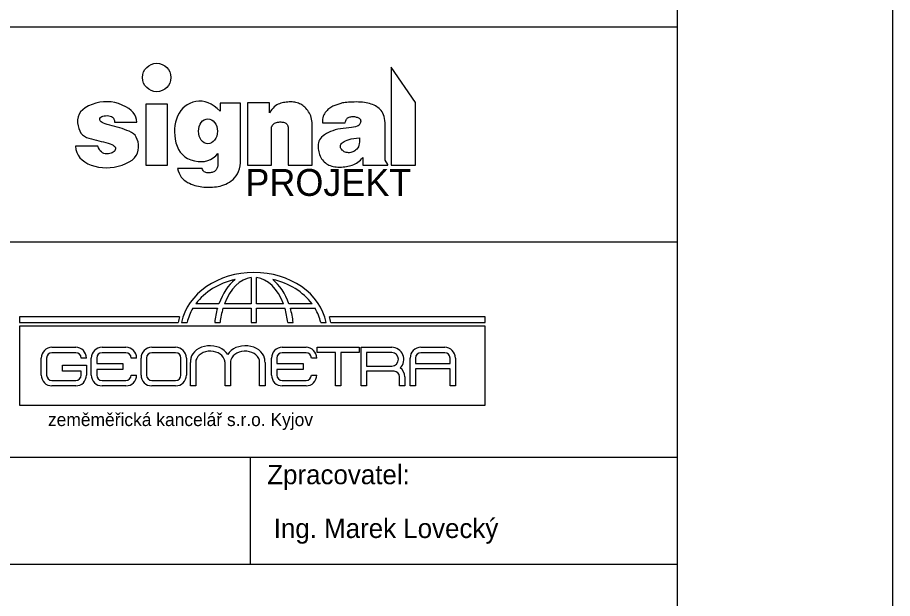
# Model space of a CAD drawing. Extents: x -553916 to -552953, y -1067470 to -1066637.
# Drawn here: x -553034.4 to -552953.1, y -1067311.4 to -1067257.4 of the extents above; entities that cross this region are included whole.
import ezdxf

# ---------------------------------------------------------------- set-up
doc = ezdxf.new("R2010")
doc.units = 0
for name, color, linetype in [('ROZPISKA', 7, 'Continuous'), ('Rozpiska_pole_1', 7, 'Continuous'), ('Rozpiska_pole_6', 7, 'Continuous'), ('Vrstva 1', 7, 'Continuous'), ('ZZZ - Razítko', 7, 'Continuous')]:
    doc.layers.add(name, color=color, linetype=linetype)

msp = doc.modelspace()

# ---------------------------------------------------------------- linework, layer by layer
at = {"layer": 'ROZPISKA'}
for points in [[(-552997.445, -1067271.147), (-552997.445, -1067265.307), (-552999.685, -1067262.027), (-552999.685, -1067271.147), (-552997.445, -1067271.147)], [(-553026.174, -1067271.382), (-553025.812, -1067271.366), (-553025.445, -1067271.318), (-553025.074, -1067271.239), (-553024.698, -1067271.128), (-553024.344, -1067270.992), (-553024.036, -1067270.836), (-553023.775, -1067270.66), (-553023.561, -1067270.464), (-553023.393, -1067270.248), (-553023.273, -1067270.012), (-553023.199, -1067269.756), (-553023.173, -1067269.481), (-553023.183, -1067269.207), (-553023.222, -1067268.958), (-553023.288, -1067268.734), (-553023.382, -1067268.535), (-553023.503, -1067268.36), (-553023.652, -1067268.21), (-553023.829, -1067268.084), (-553024.034, -1067267.984), (-553024.253, -1067267.898), (-553024.475, -1067267.816), (-553024.699, -1067267.738), (-553024.926, -1067267.666), (-553025.155, -1067267.597), (-553025.386, -1067267.533), (-553025.619, -1067267.473), (-553025.855, -1067267.418), (-553026.077, -1067267.363), (-553026.268, -1067267.304), (-553026.428, -1067267.241), (-553026.559, -1067267.174), (-553026.659, -1067267.102), (-553026.728, -1067267.027), (-553026.767, -1067266.948), (-553026.776, -1067266.865), (-553026.759, -1067266.785), (-553026.723, -1067266.717), (-553026.667, -1067266.659), (-553026.591, -1067266.611), (-553026.495, -1067266.575), (-553026.379, -1067266.55), (-553026.244, -1067266.535), (-553026.088, -1067266.531), (-553025.933, -1067266.542), (-553025.798, -1067266.571), (-553025.683, -1067266.619), (-553025.588, -1067266.684), (-553025.513, -1067266.768), (-553025.459, -1067266.87), (-553025.424, -1067266.991), (-553025.41, -1067267.129), (-553023.331, -1067267.129), (-553023.35, -1067266.888), (-553023.412, -1067266.658), (-553023.517, -1067266.441), (-553023.665, -1067266.237), (-553023.856, -1067266.045), (-553024.09, -1067265.866), (-553024.366, -1067265.7), (-553024.686, -1067265.547), (-553025.028, -1067265.417), (-553025.373, -1067265.323), (-553025.721, -1067265.263), (-553026.071, -1067265.238), (-553026.424, -1067265.248), (-553026.779, -1067265.293), (-553027.138, -1067265.373), (-553027.498, -1067265.487), (-553027.836, -1067265.63), (-553028.126, -1067265.792), (-553028.366, -1067265.976), (-553028.559, -1067266.18), (-553028.702, -1067266.404), (-553028.797, -1067266.649), (-553028.843, -1067266.914), (-553028.841, -1067267.2), (-553028.801, -1067267.482), (-553028.735, -1067267.734), (-553028.643, -1067267.956), (-553028.524, -1067268.149), (-553028.38, -1067268.312), (-553028.209, -1067268.446), (-553028.012, -1067268.55), (-553027.788, -1067268.625), (-553027.553, -1067268.685), (-553027.322, -1067268.745), (-553027.095, -1067268.804), (-553026.871, -1067268.863), (-553026.65, -1067268.921), (-553026.434, -1067268.98), (-553026.221, -1067269.038), (-553026.011, -1067269.096), (-553025.819, -1067269.156), (-553025.657, -1067269.22), (-553025.527, -1067269.289), (-553025.427, -1067269.362), (-553025.359, -1067269.44), (-553025.321, -1067269.523), (-553025.314, -1067269.609), (-553025.338, -1067269.701), (-553025.384, -1067269.789), (-553025.445, -1067269.865), (-553025.521, -1067269.93), (-553025.611, -1067269.983), (-553025.715, -1067270.024), (-553025.833, -1067270.054), (-553025.966, -1067270.073), (-553026.113, -1067270.079), (-553026.262, -1067270.069), (-553026.398, -1067270.036), (-553026.521, -1067269.98), (-553026.632, -1067269.902), (-553026.731, -1067269.8), (-553026.818, -1067269.677), (-553026.892, -1067269.53), (-553026.953, -1067269.362), (-553029.034, -1067269.362), (-553028.99, -1067269.668), (-553028.906, -1067269.951), (-553028.783, -1067270.208), (-553028.621, -1067270.442), (-553028.418, -1067270.652), (-553028.177, -1067270.837), (-553027.895, -1067270.998), (-553027.574, -1067271.134), (-553027.231, -1067271.243), (-553026.883, -1067271.321), (-553026.531, -1067271.367), (-553026.174, -1067271.382)], [(-553016.626, -1067273.189), (-553016.457, -1067273.186), (-553016.287, -1067273.177), (-553016.115, -1067273.164), (-553015.942, -1067273.145), (-553015.768, -1067273.119), (-553015.594, -1067273.08), (-553015.42, -1067273.028), (-553015.246, -1067272.965), (-553015.073, -1067272.89), (-553014.9, -1067272.802), (-553014.728, -1067272.702), (-553014.556, -1067272.59), (-553014.391, -1067272.461), (-553014.243, -1067272.308), (-553014.11, -1067272.132), (-553013.994, -1067271.933), (-553013.893, -1067271.711), (-553013.808, -1067271.466), (-553013.739, -1067271.198), (-553013.685, -1067270.907), (-553013.685, -1067265.387), (-553015.605, -1067265.387), (-553015.605, -1067266.107), (-553015.871, -1067265.853), (-553016.142, -1067265.64), (-553016.416, -1067265.468), (-553016.695, -1067265.337), (-553016.978, -1067265.247), (-553017.266, -1067265.198), (-553017.557, -1067265.19), (-553017.853, -1067265.224), (-553018.14, -1067265.292), (-553018.406, -1067265.389), (-553018.649, -1067265.514), (-553018.871, -1067265.668), (-553019.071, -1067265.85), (-553019.249, -1067266.061), (-553019.406, -1067266.301), (-553019.541, -1067266.568), (-553019.651, -1067266.854), (-553019.736, -1067267.147), (-553019.795, -1067267.447), (-553019.828, -1067267.755), (-553019.835, -1067268.069), (-553019.816, -1067268.391), (-553019.772, -1067268.72), (-553019.701, -1067269.056), (-553019.601, -1067269.379), (-553019.468, -1067269.67), (-553019.303, -1067269.928), (-553019.105, -1067270.154), (-553018.874, -1067270.346), (-553018.611, -1067270.506), (-553018.314, -1067270.634), (-553017.986, -1067270.728), (-553017.649, -1067270.786), (-553017.331, -1067270.804), (-553017.03, -1067270.78), (-553016.747, -1067270.716), (-553016.482, -1067270.612), (-553016.235, -1067270.466), (-553016.005, -1067270.28), (-553015.793, -1067270.053), (-553015.793, -1067271.13), (-553015.812, -1067271.217), (-553015.835, -1067271.299), (-553015.862, -1067271.375), (-553015.895, -1067271.445), (-553015.931, -1067271.51), (-553015.972, -1067271.568), (-553016.018, -1067271.621), (-553016.067, -1067271.669), (-553016.123, -1067271.71), (-553016.186, -1067271.747), (-553016.256, -1067271.778), (-553016.333, -1067271.803), (-553016.417, -1067271.823), (-553016.508, -1067271.838), (-553016.606, -1067271.847), (-553016.711, -1067271.851), (-553016.815, -1067271.846), (-553016.908, -1067271.827), (-553016.991, -1067271.796), (-553017.064, -1067271.751), (-553017.127, -1067271.692), (-553017.18, -1067271.621), (-553017.222, -1067271.536), (-553017.254, -1067271.438), (-553019.562, -1067271.438), (-553019.492, -1067271.665), (-553019.409, -1067271.874), (-553019.312, -1067272.064), (-553019.201, -1067272.236), (-553019.077, -1067272.388), (-553018.938, -1067272.522), (-553018.786, -1067272.637), (-553018.62, -1067272.734), (-553018.448, -1067272.817), (-553018.277, -1067272.891), (-553018.108, -1067272.956), (-553017.94, -1067273.013), (-553017.774, -1067273.062), (-553017.609, -1067273.102), (-553017.446, -1067273.133), (-553017.284, -1067273.155), (-553017.122, -1067273.171), (-553016.958, -1067273.182), (-553016.793, -1067273.188), (-553016.626, -1067273.189)], [(-553007.045, -1067271.147), (-553007.045, -1067267.347), (-553007.048, -1067267.177), (-553007.062, -1067267.014), (-553007.087, -1067266.857), (-553007.123, -1067266.707), (-553007.169, -1067266.564), (-553007.226, -1067266.427), (-553007.294, -1067266.297), (-553007.372, -1067266.173), (-553007.457, -1067266.057), (-553007.544, -1067265.949), (-553007.633, -1067265.849), (-553007.724, -1067265.757), (-553007.817, -1067265.674), (-553007.912, -1067265.598), (-553008.009, -1067265.531), (-553008.108, -1067265.473), (-553008.211, -1067265.421), (-553008.317, -1067265.377), (-553008.428, -1067265.34), (-553008.543, -1067265.309), (-553008.662, -1067265.286), (-553008.786, -1067265.269), (-553008.914, -1067265.259), (-553009.046, -1067265.257), (-553009.18, -1067265.26), (-553009.312, -1067265.268), (-553009.444, -1067265.281), (-553009.574, -1067265.299), (-553009.703, -1067265.322), (-553009.831, -1067265.35), (-553009.957, -1067265.382), (-553010.083, -1067265.42), (-553010.206, -1067265.468), (-553010.328, -1067265.533), (-553010.447, -1067265.614), (-553010.563, -1067265.712), (-553010.677, -1067265.826), (-553010.789, -1067265.957), (-553010.898, -1067266.104), (-553011.005, -1067266.267), (-553011.005, -1067265.347), (-553013.045, -1067265.347), (-553013.045, -1067271.147), (-553010.805, -1067271.147), (-553010.805, -1067267.587), (-553010.771, -1067267.496), (-553010.726, -1067267.415), (-553010.672, -1067267.344), (-553010.608, -1067267.283), (-553010.534, -1067267.232), (-553010.45, -1067267.191), (-553010.356, -1067267.16), (-553010.252, -1067267.139), (-553010.146, -1067267.126), (-553010.045, -1067267.119), (-553009.95, -1067267.118), (-553009.859, -1067267.124), (-553009.774, -1067267.135), (-553009.695, -1067267.153), (-553009.62, -1067267.176), (-553009.551, -1067267.206), (-553009.489, -1067267.241), (-553009.435, -1067267.279), (-553009.389, -1067267.321), (-553009.352, -1067267.367), (-553009.323, -1067267.417), (-553009.302, -1067267.47), (-553009.289, -1067267.527), (-553009.285, -1067267.587), (-553009.285, -1067271.147), (-553007.045, -1067271.147)], [(-553004.482, -1067271.311), (-553004.321, -1067271.308), (-553004.163, -1067271.3), (-553004.01, -1067271.285), (-553003.861, -1067271.265), (-553003.716, -1067271.24), (-553003.576, -1067271.208), (-553003.44, -1067271.171), (-553003.308, -1067271.128), (-553003.18, -1067271.076), (-553003.053, -1067271.015), (-553002.927, -1067270.943), (-553002.804, -1067270.861), (-553002.682, -1067270.768), (-553002.561, -1067270.665), (-553002.442, -1067270.551), (-553002.325, -1067270.427), (-553002.325, -1067271.147), (-553000.005, -1067271.147), (-553000.005, -1067271.067), (-553000.245, -1067270.667), (-553000.245, -1067267.187), (-553000.272, -1067266.983), (-553000.307, -1067266.792), (-553000.353, -1067266.617), (-553000.408, -1067266.456), (-553000.472, -1067266.309), (-553000.546, -1067266.177), (-553000.63, -1067266.059), (-553000.723, -1067265.955), (-553000.824, -1067265.863), (-553000.931, -1067265.777), (-553001.045, -1067265.698), (-553001.165, -1067265.626), (-553001.291, -1067265.561), (-553001.423, -1067265.503), (-553001.562, -1067265.452), (-553001.707, -1067265.408), (-553001.859, -1067265.37), (-553002.018, -1067265.338), (-553002.184, -1067265.311), (-553002.358, -1067265.29), (-553002.538, -1067265.275), (-553002.726, -1067265.266), (-553002.922, -1067265.262), (-553003.124, -1067265.265), (-553003.323, -1067265.271), (-553003.507, -1067265.279), (-553003.676, -1067265.289), (-553003.83, -1067265.302), (-553003.97, -1067265.317), (-553004.095, -1067265.334), (-553004.206, -1067265.354), (-553004.301, -1067265.375), (-553004.39, -1067265.399), (-553004.479, -1067265.425), (-553004.569, -1067265.452), (-553004.66, -1067265.482), (-553004.751, -1067265.513), (-553004.844, -1067265.547), (-553004.936, -1067265.582), (-553005.03, -1067265.62), (-553005.123, -1067265.661), (-553005.215, -1067265.71), (-553005.306, -1067265.765), (-553005.397, -1067265.827), (-553005.486, -1067265.896), (-553005.574, -1067265.972), (-553005.661, -1067266.055), (-553005.747, -1067266.144), (-553005.827, -1067266.242), (-553005.897, -1067266.349), (-553005.955, -1067266.465), (-553006.003, -1067266.591), (-553006.04, -1067266.726), (-553006.066, -1067266.87), (-553006.081, -1067267.024), (-553006.085, -1067267.187), (-553003.965, -1067267.187), (-553003.95, -1067267.091), (-553003.926, -1067267.004), (-553003.893, -1067266.926), (-553003.851, -1067266.857), (-553003.801, -1067266.797), (-553003.743, -1067266.747), (-553003.675, -1067266.705), (-553003.599, -1067266.673), (-553003.519, -1067266.649), (-553003.438, -1067266.631), (-553003.356, -1067266.619), (-553003.274, -1067266.615), (-553003.192, -1067266.616), (-553003.108, -1067266.625), (-553003.025, -1067266.639), (-553002.94, -1067266.661), (-553002.86, -1067266.686), (-553002.789, -1067266.714), (-553002.726, -1067266.744), (-553002.673, -1067266.776), (-553002.627, -1067266.81), (-553002.591, -1067266.846), (-553002.563, -1067266.885), (-553002.545, -1067266.925), (-553002.533, -1067266.968), (-553002.528, -1067267.014), (-553002.529, -1067267.063), (-553002.537, -1067267.114), (-553002.55, -1067267.168), (-553002.57, -1067267.225), (-553002.597, -1067267.285), (-553002.629, -1067267.348), (-553002.68, -1067267.409), (-553002.761, -1067267.465), (-553002.872, -1067267.515), (-553003.014, -1067267.561), (-553003.186, -1067267.601), (-553003.388, -1067267.636), (-553003.621, -1067267.665), (-553003.884, -1067267.689), (-553004.156, -1067267.716), (-553004.415, -1067267.753), (-553004.662, -1067267.801), (-553004.897, -1067267.86), (-553005.12, -1067267.929), (-553005.331, -1067268.008), (-553005.529, -1067268.098), (-553005.715, -1067268.199), (-553005.884, -1067268.307), (-553006.032, -1067268.42), (-553006.16, -1067268.537), (-553006.266, -1067268.659), (-553006.352, -1067268.785), (-553006.417, -1067268.915), (-553006.461, -1067269.051), (-553006.484, -1067269.19), (-553006.492, -1067269.332), (-553006.491, -1067269.472), (-553006.481, -1067269.611), (-553006.462, -1067269.749), (-553006.434, -1067269.885), (-553006.397, -1067270.021), (-553006.351, -1067270.155), (-553006.296, -1067270.288), (-553006.233, -1067270.417), (-553006.163, -1067270.536), (-553006.086, -1067270.646), (-553006.002, -1067270.748), (-553005.911, -1067270.84), (-553005.814, -1067270.924), (-553005.709, -1067270.999), (-553005.598, -1067271.065), (-553005.48, -1067271.123), (-553005.356, -1067271.173), (-553005.226, -1067271.215), (-553005.089, -1067271.25), (-553004.947, -1067271.277), (-553004.798, -1067271.296), (-553004.643, -1067271.307), (-553004.482, -1067271.311)], [(-553020.485, -1067271.147), (-553020.485, -1067265.467), (-553022.485, -1067265.467), (-553022.485, -1067271.147), (-553020.485, -1067271.147)], [(-553003.767, -1067269.967), (-553003.87, -1067269.946), (-553003.964, -1067269.918), (-553004.051, -1067269.882), (-553004.13, -1067269.839), (-553004.201, -1067269.787), (-553004.264, -1067269.728), (-553004.319, -1067269.661), (-553004.365, -1067269.587), (-553004.4, -1067269.509), (-553004.418, -1067269.432), (-553004.419, -1067269.356), (-553004.403, -1067269.281), (-553004.371, -1067269.207), (-553004.322, -1067269.134), (-553004.256, -1067269.061), (-553004.173, -1067268.99), (-553004.07, -1067268.922), (-553003.941, -1067268.859), (-553003.787, -1067268.801), (-553003.608, -1067268.748), (-553003.404, -1067268.701), (-553003.175, -1067268.659), (-553002.92, -1067268.623), (-553002.64, -1067268.592), (-553002.636, -1067268.79), (-553002.645, -1067268.972), (-553002.667, -1067269.138), (-553002.701, -1067269.288), (-553002.749, -1067269.421), (-553002.809, -1067269.539), (-553002.882, -1067269.64), (-553002.969, -1067269.725), (-553003.062, -1067269.797), (-553003.158, -1067269.856), (-553003.255, -1067269.904), (-553003.354, -1067269.94), (-553003.454, -1067269.964), (-553003.557, -1067269.977), (-553003.661, -1067269.978), (-553003.767, -1067269.967)]]:
    msp.add_lwpolyline(points, dxfattribs=at)
msp.add_circle((-553021.485, -1067262.987), 1.32, dxfattribs=at)
msp.add_ellipse((-553016.725, -1067267.987), major_axis=(0, 1.16), ratio=0.758621, dxfattribs=at)
at = {"layer": 'Rozpiska_pole_1'}
msp.add_lwpolyline([(-553143.11, -1067133.268), (-552973.11, -1067133.268), (-552973.11, -1067393.268), (-553143.11, -1067393.268)], close=True, dxfattribs=at)
at = {"layer": 'Rozpiska_pole_6'}
for p, q in [((-553143.11, -1067278.268), (-552973.11, -1067278.268)), ((-553143.11, -1067298.268), (-552973.11, -1067298.268)), ((-553012.76, -1067308.268), (-553012.76, -1067298.268))]:
    msp.add_line(p, q, dxfattribs=at)
msp.add_lwpolyline([(-553143.11, -1067258.268), (-552973.11, -1067258.268), (-552973.11, -1067308.268), (-553143.11, -1067308.268)], close=True, dxfattribs=at)
at = {"layer": 'Vrstva 1'}
msp.add_line((-552953.11, -1066816.268), (-552953.11, -1067410.268), dxfattribs=at)
at = {"layer": 'ZZZ - Razítko'}
for p, q in [((-553012.715, -1067281.581), (-553012.715, -1067284.027)), ((-553012.208, -1067284.027), (-553012.208, -1067281.579)), ((-553015.708, -1067284.027), (-553017.853, -1067284.027)), ((-553012.715, -1067284.027), (-553015.191, -1067284.027)), ((-553009.713, -1067284.027), (-553012.208, -1067284.027)), ((-553007.051, -1067284.027), (-553009.196, -1067284.027)), ((-553018.128, -1067284.438), (-553015.841, -1067284.438)), ((-553015.331, -1067284.438), (-553012.715, -1067284.438)), ((-553012.715, -1067284.438), (-553012.715, -1067285.758)), ((-553012.208, -1067285.758), (-553012.208, -1067284.438)), ((-553012.208, -1067284.438), (-553009.574, -1067284.438)), ((-553009.064, -1067284.438), (-553006.776, -1067284.438)), ((-553019.359, -1067285.227), (-553034.239, -1067285.227)), ((-553034.239, -1067285.227), (-553034.239, -1067285.758)), ((-552990.961, -1067285.227), (-553005.439, -1067285.227)), ((-552990.961, -1067285.758), (-552990.961, -1067285.227)), ((-552990.963, -1067286.103), (-553034.246, -1067286.103)), ((-553034.246, -1067286.103), (-553034.246, -1067293.441)), ((-553034.239, -1067285.758), (-553019.497, -1067285.758)), ((-553019.171, -1067285.758), (-553018.654, -1067285.758)), ((-553016.098, -1067285.758), (-553015.598, -1067285.758)), ((-553012.715, -1067285.758), (-553012.208, -1067285.758)), ((-553009.307, -1067285.758), (-553008.806, -1067285.758)), ((-553006.25, -1067285.758), (-553005.733, -1067285.758)), ((-553005.301, -1067285.758), (-552990.961, -1067285.758)), ((-552990.963, -1067293.441), (-552990.963, -1067286.103)), ((-553031.221, -1067288.069), (-553029.01, -1067288.069)), ((-553026.565, -1067288.069), (-553024.354, -1067288.069)), ((-553021.941, -1067288.069), (-553019.73, -1067288.069)), ((-553009.822, -1067288.069), (-553007.612, -1067288.069)), ((-553002.485, -1067288.069), (-552999.64, -1067288.069)), ((-552996.937, -1067288.069), (-552994.726, -1067288.069)), ((-553029.01, -1067288.567), (-553031.221, -1067288.567)), ((-553024.354, -1067288.567), (-553026.565, -1067288.567)), ((-553019.73, -1067288.567), (-553021.941, -1067288.567)), ((-553007.612, -1067288.567), (-553009.822, -1067288.567)), ((-553004.879, -1067291.651), (-553004.879, -1067288.555)), ((-553004.376, -1067288.555), (-553004.376, -1067291.651)), ((-552999.64, -1067288.558), (-553001.981, -1067288.558)), ((-553001.981, -1067288.558), (-553001.981, -1067289.807)), ((-552994.726, -1067288.567), (-552996.937, -1067288.567)), ((-553032.219, -1067290.653), (-553032.219, -1067289.067)), ((-553031.72, -1067289.067), (-553031.72, -1067290.653)), ((-553030.246, -1067290.275), (-553030.246, -1067289.73)), ((-553030.246, -1067289.73), (-553028.013, -1067289.73)), ((-553028.013, -1067289.067), (-553028.511, -1067289.067)), ((-553028.013, -1067289.73), (-553028.013, -1067290.653)), ((-553027.562, -1067290.653), (-553027.562, -1067289.067)), ((-553027.064, -1067289.067), (-553027.064, -1067289.577)), ((-553027.064, -1067289.577), (-553024.621, -1067289.577)), ((-553024.621, -1067289.577), (-553024.621, -1067290.122)), ((-553023.356, -1067289.067), (-553023.855, -1067289.067)), ((-553022.939, -1067290.653), (-553022.939, -1067289.067)), ((-553022.44, -1067289.067), (-553022.44, -1067290.653)), ((-553019.231, -1067290.653), (-553019.231, -1067289.067)), ((-553018.732, -1067289.067), (-553018.732, -1067290.653)), ((-553018.36, -1067291.651), (-553018.36, -1067289.466)), ((-553017.859, -1067289.466), (-553017.859, -1067291.651)), ((-553015.14, -1067291.651), (-553015.14, -1067289.466)), ((-553014.639, -1067289.466), (-553014.639, -1067291.651)), ((-553011.921, -1067291.651), (-553011.921, -1067289.466)), ((-553011.42, -1067289.466), (-553011.42, -1067291.651)), ((-553010.82, -1067290.653), (-553010.82, -1067289.067)), ((-553010.321, -1067289.067), (-553010.321, -1067289.577)), ((-553010.321, -1067289.577), (-553007.878, -1067289.577)), ((-553007.878, -1067289.577), (-553007.878, -1067290.122)), ((-553006.614, -1067289.067), (-553007.112, -1067289.067)), ((-552997.935, -1067291.651), (-552997.935, -1067289.067)), ((-552997.436, -1067289.067), (-552997.436, -1067289.575)), ((-552997.436, -1067289.575), (-552994.227, -1067289.575)), ((-552994.227, -1067289.575), (-552994.227, -1067289.067)), ((-552993.728, -1067289.067), (-552993.728, -1067291.651)), ((-553028.511, -1067290.275), (-553030.246, -1067290.275)), ((-553028.511, -1067290.653), (-553028.511, -1067290.275)), ((-553024.621, -1067290.122), (-553027.064, -1067290.122)), ((-553027.064, -1067290.122), (-553027.064, -1067290.653)), ((-553007.878, -1067290.122), (-553010.321, -1067290.122)), ((-553010.321, -1067290.122), (-553010.321, -1067290.653)), ((-553001.981, -1067289.807), (-552999.64, -1067289.807)), ((-552999.64, -1067290.296), (-553001.981, -1067290.296)), ((-552999.426, -1067290.3), (-552999.64, -1067290.296)), ((-552994.227, -1067290.079), (-552997.436, -1067290.079)), ((-552997.436, -1067290.079), (-552997.436, -1067291.651)), ((-552994.227, -1067291.651), (-552994.227, -1067290.079)), ((-553031.221, -1067291.152), (-553029.01, -1067291.152)), ((-553026.565, -1067291.152), (-553024.354, -1067291.152)), ((-553023.855, -1067290.653), (-553023.356, -1067290.653)), ((-553021.941, -1067291.152), (-553019.73, -1067291.152)), ((-553009.822, -1067291.152), (-553007.612, -1067291.152)), ((-553007.112, -1067290.653), (-553006.614, -1067290.653)), ((-552998.927, -1067291.651), (-552998.927, -1067290.799)), ((-552998.429, -1067290.799), (-552998.429, -1067291.651)), ((-553029.01, -1067291.651), (-553031.221, -1067291.651)), ((-553024.354, -1067291.651), (-553026.565, -1067291.651)), ((-553019.73, -1067291.651), (-553021.941, -1067291.651)), ((-553017.859, -1067291.651), (-553018.36, -1067291.651)), ((-553014.639, -1067291.651), (-553015.14, -1067291.651)), ((-553011.42, -1067291.651), (-553011.921, -1067291.651)), ((-553007.612, -1067291.651), (-553009.822, -1067291.651)), ((-553004.376, -1067291.651), (-553004.879, -1067291.651)), ((-552998.429, -1067291.651), (-552998.927, -1067291.651)), ((-552997.436, -1067291.651), (-552997.935, -1067291.651)), ((-552993.728, -1067291.651), (-552994.227, -1067291.651)), ((-553034.246, -1067293.441), (-552990.963, -1067293.441))]:
    msp.add_line(p, q, dxfattribs=at)
for points in [[(-553004.879, -1067288.555), (-553006.577, -1067288.555), (-553006.577, -1067288.069), (-553002.663, -1067288.069)], [(-553002.663, -1067288.069), (-553002.663, -1067288.555), (-553004.376, -1067288.555)], [(-553001.981, -1067290.296), (-553001.981, -1067291.651), (-553002.485, -1067291.651), (-553002.485, -1067288.069)]]:
    msp.add_lwpolyline(points, dxfattribs=at)
for centre, radius, start, end in [((-553031.221, -1067289.067), 0.998, 90, 180), ((-553029.01, -1067289.067), 0.998, 360, 90), ((-553026.565, -1067289.067), 0.998, 90, 180), ((-553024.354, -1067289.067), 0.998, 360, 90), ((-553021.941, -1067289.067), 0.998, 90, 180), ((-553019.73, -1067289.067), 0.998, 360, 90), ((-553009.822, -1067289.067), 0.998, 90, 180), ((-553007.612, -1067289.067), 0.998, 360, 90), ((-552999.64, -1067289.183), 1.114, 314.45734, 90), ((-552996.937, -1067289.067), 0.998, 90, 180), ((-552994.726, -1067289.067), 0.998, 360, 90), ((-553031.221, -1067289.067), 0.499, 90, 180), ((-553029.01, -1067289.067), 0.499, 0, 90), ((-553026.565, -1067289.067), 0.499, 90, 180), ((-553024.354, -1067289.067), 0.499, 0, 90), ((-553021.941, -1067289.067), 0.499, 90, 180), ((-553019.73, -1067289.067), 0.499, 0, 90), ((-553009.822, -1067289.067), 0.499, 90, 180), ((-553007.612, -1067289.067), 0.499, 0, 90), ((-552999.64, -1067289.183), 0.625, 270, 90), ((-552996.937, -1067289.067), 0.499, 90, 180), ((-552994.726, -1067289.067), 0.499, 0, 90), ((-553016.422, -1067289.516), 1.938, 166.96576, 178.52091), ((-553016.094, -1067289.53), 0.957, 3.86486, 22.41569), ((-553013.407, -1067289.588), 1.238, 162.61388, 174.3506), ((-553013.358, -1067289.516), 1.938, 1.47909, 13.03424), ((-552999.426, -1067290.799), 0.499, 0, 90), ((-552999.426, -1067290.799), 0.998, 360, 55.44734), ((-553031.221, -1067290.653), 0.998, 180, 270), ((-553031.221, -1067290.653), 0.499, 180, 270), ((-553029.01, -1067290.653), 0.998, 270, 0), ((-553029.01, -1067290.653), 0.499, 270, 0), ((-553026.565, -1067290.653), 0.998, 180, 270), ((-553026.565, -1067290.653), 0.499, 180, 270), ((-553024.354, -1067290.653), 0.998, 270, 0), ((-553024.354, -1067290.653), 0.499, 270, 0), ((-553021.941, -1067290.653), 0.998, 180, 270), ((-553021.941, -1067290.653), 0.499, 180, 270), ((-553019.73, -1067290.653), 0.998, 270, 0), ((-553019.73, -1067290.653), 0.499, 270, 0), ((-553009.822, -1067290.653), 0.998, 180, 270), ((-553009.822, -1067290.653), 0.499, 180, 270), ((-553007.612, -1067290.653), 0.998, 270, 0), ((-553007.612, -1067290.653), 0.499, 270, 0)]:
    msp.add_arc(centre, radius, start, end, dxfattribs=at)
for centre, major_axis, ratio, start_param, end_param in [((-553012.452, -1067286.631), (-6.804, 0), 0.811768, 3.300239, 6.124539), ((-553012.452, -1067286.631), (0, 5.067), 0.630136, 0.08224, 1.030995), ((-553012.452, -1067286.631), (0, 5.067), 0.630136, 5.252191, 6.206521), ((-553012.452, -1067286.631), (-6.296, 0), 0.804826, 4.992897, 5.743383), ((-553012.452, -1067286.631), (0, 5.524), 0.668443, 0.491666, 1.079789), ((-553012.452, -1067286.631), (0, 5.524), 0.668443, 5.203397, 5.79152), ((-553012.452, -1067286.631), (-6.296, 0), 0.804826, 3.681394, 4.431881), ((-553012.452, -1067286.631), (-6.296, 0), 0.804826, 5.835664, 6.110118), ((-553012.452, -1067286.631), (0, 5.524), 0.668443, 1.16256, 1.41215), ((-553012.452, -1067286.631), (0, 5.067), 0.630136, 1.123275, 1.397729), ((-553012.452, -1067286.631), (0, 5.067), 0.630136, 4.885456, 5.159911), ((-553012.452, -1067286.631), (0, 5.524), 0.668443, 4.871035, 5.120625), ((-553012.452, -1067286.631), (-6.296, 0), 0.804826, 3.31466, 3.589114), ((-553012.778, -1067286.631), (-6.804, 0), 0.811768, 6.026233, 6.124539), ((-553012.02, -1067286.631), (-6.804, 0), 0.811768, 3.300239, 3.398545), ((-553016.531, -1067289.31), (1.805, 0), 0.766187, 0.429647, 2.97338), ((-553013.249, -1067289.31), (-1.805, 0), 0.766187, 3.309805, 5.853538), ((-553016.506, -1067289.466), (1.354, 0), 0.766187, 0.29376, 3.141593), ((-553013.274, -1067289.466), (-1.354, 0), 0.766187, 3.141593, 6.041607)]:
    msp.add_ellipse(centre, major_axis=major_axis, ratio=ratio, start_param=start_param, end_param=end_param, dxfattribs=at)

# ---------------------------------------------------------------- texts
at = {"layer": 'ROZPISKA'}
msp.add_text('PROJEKT', height=2.5, dxfattribs=at).set_placement((-553013.245, -1067273.99))
at = {"layer": 'Rozpiska_pole_6'}
for s, p in [('Zpracovatel:', (-553011.214, -1067300.795)), ('Ing. Marek Lovecký', (-553010.613, -1067305.795))]:
    msp.add_text(s, height=1.8, dxfattribs=at).set_placement(p)
at = {"layer": 'ZZZ - Razítko'}
msp.add_text('zeměměřická kancelář s.r.o. Kyjov', height=1.20984, dxfattribs=at).set_placement((-553031.594, -1067295.39))

doc.saveas('drawing.dxf')
